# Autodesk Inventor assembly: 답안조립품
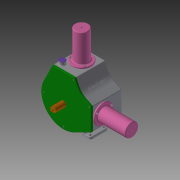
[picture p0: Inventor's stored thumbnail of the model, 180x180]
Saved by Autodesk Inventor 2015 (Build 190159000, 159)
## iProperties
Created: 2022-01
Part Number: 답안조립품
Document SubType Name: Assembly
Designer: user
Author: user
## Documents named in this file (13)
- C:\Users\user\Desktop\620117V1011\답안조립품.iam
- C:\Users\user\Desktop\620117V1011\너트 M3.ipt
- C:\Users\user\Desktop\620117V1011\베어링 20 x 37 x 9.ipt
- C:\Users\user\Desktop\620117V1011\본체.ipt
- C:\Users\user\Desktop\620117V1011\볼트 M3 x 12.ipt
- C:\Users\user\Desktop\620117V1011\실린더.ipt
- C:\Users\user\Desktop\620117V1011\앞커버.ipt
- C:\Users\user\Desktop\620117V1011\축.ipt
- C:\Users\user\Desktop\620117V1011\측정게이지.ipt
- C:\Users\user\Desktop\620117V1011\커넥팅로드 캡.ipt
- C:\Users\user\Desktop\620117V1011\커넥팅로드.ipt
- C:\Users\user\Desktop\620117V1011\피스톤 핀.ipt
- C:\Users\user\Desktop\620117V1011\피스톤.ipt
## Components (4 placed, 2 different names)
1. 피스톤 핀:1
2. 피스톤:1
3. 피스톤:2
4. 피스톤 핀:2
